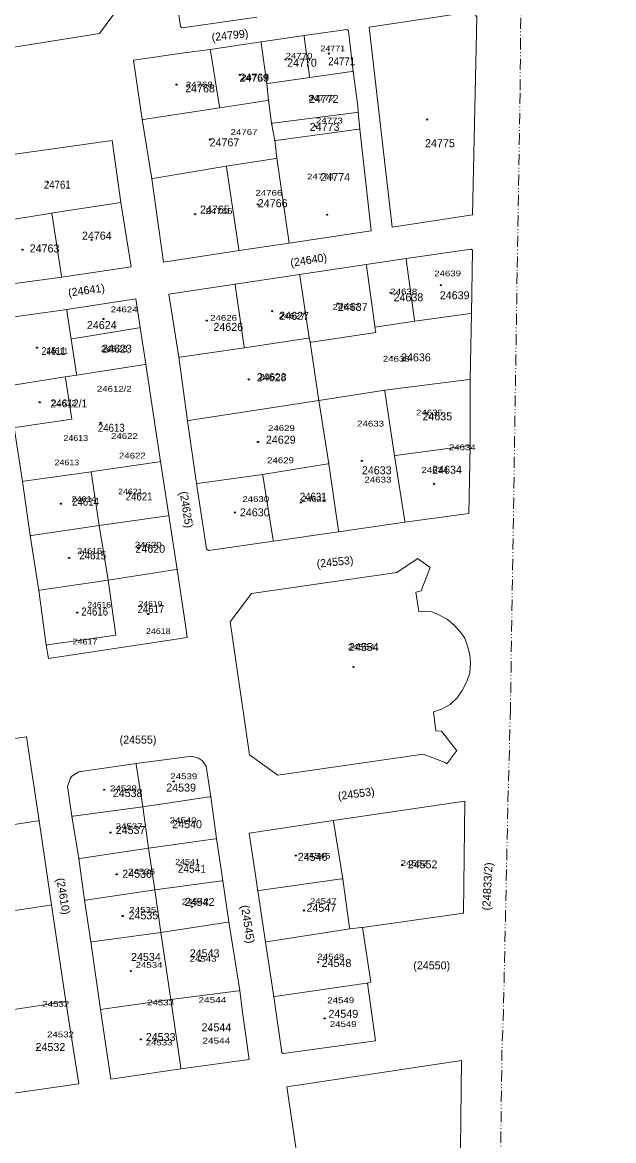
# Model space of a CAD drawing. Extents: x 649608 to 651081, y 237980 to 241202.
# Drawn here: x 650339 to 650605, y 239441 to 239944 of the extents above; entities that cross this region are included whole.
import ezdxf

# ---------------------------------------------------------------- set-up
doc = ezdxf.new("R2010")
doc.units = 0
doc.header["$PDMODE"] = 32
doc.header["$PDSIZE"] = 0.5
doc.linetypes.add('DASH_DOUBLE_DOT', pattern=[9.2, 5, -1.2, 0.3, -1.2, 0.3, -1.2])
for name, color, linetype in [('19', 7, 'Continuous'), ('20', 7, 'Continuous'), ('6', 7, 'Continuous')]:
    doc.layers.add(name, color=color, linetype=linetype)
for name, color, linetype, lineweight in [('3', 7, 'Continuous', 13), ('5', 7, 'Continuous', 13), ('52', 7, 'DASH_DOUBLE_DOT', 13)]:
    doc.layers.add(name, color=color, linetype=linetype, lineweight=lineweight)

msp = doc.modelspace()

# ---------------------------------------------------------------- linework, layer by layer
at = {"layer": '3'}
for p, q in [((650388.272, 239833.948), (650357.01, 239829.262)), ((650498.192, 239485.801), (650494.588, 239511.725))]:
    msp.add_line(p, q, dxfattribs=at)
for points in [[(650379.366, 240006.183), (650386.357, 239955.842), (650374.029, 239938.824), (650309.84, 239928.724), (650300.505, 239993.965)], [(650541.896, 239857.35), (650505.729, 239851.839), (650495.324, 239941.714), (650540.294, 239948.511), (650542.677, 239948.068), (650543.767, 239946.296)], [(650442.311, 239687.015), (650507.764, 239696.364), (650516.54, 239702.276), (650517.154, 239702.698), (650522.83, 239698.633), (650518.685, 239688.139), (650516.424, 239687.616), (650517.648, 239678.967), (650520.433, 239679.099), (650523.564, 239678.716), (650526.782, 239677.466), (650530.542, 239675.342), (650533.559, 239672.695), (650536.443, 239669.593), (650538.447, 239666.861), (650539.773, 239662.869), (650540.677, 239659.443), (650540.997, 239655.798), (650540.595, 239651.375), (650539.316, 239647.477), (650537.275, 239643.361), (650535.02, 239640.115), (650531.858, 239637.088), (650527.953, 239634.989), (650524.265, 239633.829), (650525.363, 239625.233), (650527.891, 239625.14), (650534.407, 239616.759), (650534.882, 239616.42), (650530.279, 239610.413), (650529.63, 239610.933), (650519.725, 239614.737), (650454.269, 239605.236), (650441.468, 239614.46), (650432.74, 239674.295)], [(650458.309, 239465.099), (650536.901, 239476.918), (650535.05, 239318.891), (650481.294, 239310.911)]]:
    msp.add_lwpolyline(points, close=True, dxfattribs=at)
for points in [[(650444.775, 239946.285), (650411.125, 239941.373), (650410.377, 239941.975), (650405.07, 239979.206), (650402.654, 239996.132)], [(650488.095, 239921.796), (650486.117, 239940.058), (650485.368, 239940.661), (650466.029, 239937.979), (650446.664, 239935.198), (650423.852, 239931.653)], [(650423.852, 239931.653), (650412.235, 239930.218), (650389.198, 239926.874), (650393.187, 239900.129), (650397.48, 239873.581)], [(650490.451, 239903.516), (650490.196, 239906.165), (650488.095, 239921.796)], [(650496.295, 239850.186), (650491.187, 239895.879), (650490.451, 239903.516)], [(650321.799, 239853.182), (650317.627, 239882.113), (650379.619, 239890.818), (650383.547, 239862.808), (650388.272, 239833.948)], [(650397.48, 239873.581), (650402.708, 239836.053), (650436.814, 239841.284), (650459.347, 239844.508), (650496.295, 239850.186)], [(650357.01, 239829.262), (650326.82, 239825.19), (650325.994, 239825.713), (650321.799, 239853.182)], [(650511.937, 239837.685), (650541.236, 239841.916), (650541.884, 239841.364), (650541.464, 239812.971)], [(650409.675, 239793.272), (650405.196, 239821.584), (650435.026, 239826.183), (650464.05, 239830.541), (650494.054, 239834.94), (650511.937, 239837.685)], [(650392.332, 239806.607), (650390.258, 239819.533), (650359.246, 239814.696)], [(650359.246, 239814.696), (650327.911, 239810.334), (650332.626, 239780.357), (650335.48, 239761.64), (650339.366, 239737.428), (650342.823, 239713.047), (650346.63, 239688.414), (650350.01, 239663.76), (650350.962, 239657.72), (650413.463, 239667.216)], [(650541.464, 239812.971), (650540.883, 239783.388), (650540.883, 239783.36), (650540.878, 239753.602), (650540.262, 239722.952)], [(650401.384, 239746.357), (650397.603, 239771.089), (650394.853, 239790.078), (650392.332, 239806.607)], [(650452.216, 239710.482), (650423.043, 239706.324), (650422.196, 239707.151), (650417.601, 239736.457), (650413.598, 239764.666), (650409.675, 239793.272)], [(650413.463, 239667.216), (650412.632, 239672.808), (650408.903, 239697.788), (650405.219, 239722.022), (650401.384, 239746.357)], [(650540.262, 239722.952), (650511.468, 239719.039), (650481.616, 239714.738), (650452.216, 239710.482)], [(650284.846, 239575.429), (650278.795, 239613.56), (650341.039, 239622.462), (650346.869, 239584.804), (650352.295, 239546.902), (650358.829, 239503.479)], [(650361.555, 239586.833), (650359.535, 239600.131), (650360.695, 239603.67), (650361.559, 239604.779), (650364.59, 239606.738), (650390.419, 239610.578)], [(650390.419, 239610.578), (650415.491, 239613.879), (650418.522, 239612.934), (650420.295, 239611.727), (650422.032, 239609.303), (650424.049, 239595.534), (650426.7, 239576.72), (650429.501, 239557.755), (650432.255, 239539.238), (650437.089, 239508.366), (650438.17, 239499.693)], [(650537.787, 239543.236), (650538.446, 239593.62), (650479.217, 239584.865)], [(650374.421, 239499.815), (650370.011, 239530.262), (650367.233, 239548.978), (650364.607, 239567.792), (650361.555, 239586.833)], [(650479.217, 239584.865), (650441.39, 239579.121), (650445.262, 239553.321), (650448.655, 239530.156), (650452.412, 239505.573)], [(650494.588, 239511.725), (650496.074, 239512.109), (650492.393, 239536.815), (650537.787, 239543.236)], [(650452.412, 239505.573), (650456.032, 239480.584), (650456.722, 239480.017), (650498.192, 239485.801)], [(650358.829, 239503.479), (650364.595, 239466.403), (650333.35, 239461.895)], [(650410.619, 239473.149), (650379.022, 239468.552), (650374.421, 239499.815)], [(650438.17, 239499.693), (650441.38, 239477.395), (650410.619, 239473.149)]]:
    msp.add_lwpolyline(points, dxfattribs=at)
at = {"layer": '5'}
msp.add_line((650374.421, 239499.815), (650406.058, 239504.324), dxfattribs=at)
for points in [[(650468.63, 239919.116), (650468.561, 239919.616), (650466.098, 239937.479), (650466.029, 239937.979)], [(650446.664, 239935.198), (650446.734, 239934.698), (650449.29, 239916.309), (650450.08, 239908.831), (650451.448, 239898.542), (650452.837, 239890.711), (650453.799, 239882.759), (650459.347, 239844.508)], [(650428.122, 239905.378), (650428.041, 239905.878), (650423.933, 239931.153), (650423.852, 239931.653)], [(650468.63, 239919.116), (650487.595, 239921.727), (650488.095, 239921.796)], [(650449.29, 239916.309), (650449.79, 239916.382), (650468.63, 239919.116)], [(650450.08, 239908.831), (650449.58, 239908.752), (650428.122, 239905.378)], [(650428.122, 239905.378), (650393.687, 239900.204), (650393.187, 239900.129)], [(650490.451, 239903.516), (650489.698, 239903.42), (650451.948, 239898.606), (650451.448, 239898.542)], [(650491.187, 239895.879), (650490.687, 239895.812), (650453.337, 239890.778), (650452.837, 239890.711)], [(650453.799, 239882.759), (650453.299, 239882.681), (650430.986, 239879.215)], [(650430.986, 239879.215), (650397.98, 239873.665), (650397.48, 239873.581)], [(650436.814, 239841.284), (650436.737, 239841.784), (650431.063, 239878.715), (650430.986, 239879.215)], [(650352.561, 239858.096), (650353.061, 239858.172), (650383.547, 239862.808)], [(650352.561, 239858.096), (650322.299, 239853.262), (650321.799, 239853.182)], [(650357.01, 239829.262), (650356.933, 239829.762), (650352.561, 239858.096)], [(650515.863, 239809.476), (650515.793, 239809.976), (650512.007, 239837.185), (650511.937, 239837.685)], [(650497.906, 239806.857), (650497.837, 239807.357), (650494.123, 239834.44), (650494.054, 239834.94)], [(650439.225, 239797.451), (650439.152, 239797.951), (650435.099, 239825.683), (650435.026, 239826.183)], [(650464.05, 239830.541), (650464.125, 239830.041), (650468.35, 239801.932), (650468.836, 239800.042), (650472.705, 239773.795), (650477.182, 239745.333)], [(650359.246, 239814.696), (650359.318, 239814.196), (650361.166, 239801.424)], [(650515.863, 239809.476), (650540.964, 239812.903), (650541.464, 239812.971)], [(650361.166, 239801.424), (650361.666, 239801.507), (650391.832, 239806.524), (650392.332, 239806.607)], [(650468.836, 239800.042), (650469.336, 239800.116), (650498.363, 239804.42), (650497.906, 239806.857), (650515.863, 239809.476)], [(650361.166, 239801.424), (650363.612, 239785.742), (650363.69, 239785.242)], [(650468.35, 239801.932), (650467.85, 239801.855), (650439.225, 239797.451)], [(650439.225, 239797.451), (650410.175, 239793.343), (650409.675, 239793.272)], [(650363.69, 239785.242), (650394.353, 239790), (650394.853, 239790.078)], [(650332.626, 239780.357), (650333.126, 239780.435), (650358.508, 239784.395), (650363.69, 239785.242)], [(650358.508, 239784.395), (650358.588, 239783.895), (650361.534, 239765.379), (650335.98, 239761.712), (650335.48, 239761.64)], [(650502.389, 239778.491), (650502.41, 239778.494), (650540.408, 239783.3), (650540.883, 239783.36)], [(650413.598, 239764.666), (650414.098, 239764.743), (650472.705, 239773.795), (650502.389, 239778.491)], [(650502.389, 239778.491), (650502.459, 239778.019), (650506.752, 239748.942)], [(650506.752, 239748.942), (650507.252, 239749.01), (650540.878, 239753.602)], [(650370.248, 239741.72), (650370.748, 239741.794), (650400.884, 239746.283), (650401.384, 239746.357)], [(650506.752, 239748.942), (650511.389, 239719.539), (650511.468, 239719.039)], [(650370.248, 239741.72), (650339.866, 239737.497), (650339.366, 239737.428)], [(650350.01, 239663.76), (650350.51, 239663.832), (650381.346, 239668.296), (650377.791, 239693.026), (650373.858, 239717.536), (650370.248, 239741.72)], [(650477.182, 239745.333), (650476.682, 239745.252), (650447.401, 239740.511)], [(650477.182, 239745.333), (650481.544, 239715.238), (650481.616, 239714.738)], [(650447.401, 239740.511), (650418.101, 239736.525), (650417.601, 239736.457)], [(650447.401, 239740.511), (650447.481, 239740.011), (650452.136, 239710.982), (650452.216, 239710.482)], [(650373.858, 239717.536), (650404.719, 239721.95), (650405.219, 239722.022)], [(650342.823, 239713.047), (650343.323, 239713.119), (650373.858, 239717.536)], [(650377.791, 239693.026), (650408.403, 239697.711), (650408.903, 239697.788)], [(650346.63, 239688.414), (650347.13, 239688.488), (650377.791, 239693.026)], [(650390.419, 239610.578), (650390.498, 239610.078), (650393.517, 239591.04), (650396.094, 239572.376), (650398.846, 239553.635), (650401.621, 239534.498), (650406.058, 239504.324)], [(650393.517, 239591.04), (650423.549, 239595.46), (650424.049, 239595.534)], [(650361.555, 239586.833), (650362.055, 239586.899), (650393.517, 239591.04)], [(650284.846, 239575.429), (650285.346, 239575.505), (650346.369, 239584.728), (650346.869, 239584.804)], [(650483.438, 239558.689), (650479.298, 239584.365), (650479.217, 239584.865)], [(650396.094, 239572.376), (650426.2, 239576.649), (650426.7, 239576.72)], [(650364.607, 239567.792), (650365.107, 239567.865), (650396.094, 239572.376)], [(650398.846, 239553.635), (650429.001, 239557.688), (650429.501, 239557.755)], [(650445.262, 239553.321), (650445.762, 239553.391), (650482.938, 239558.619), (650483.438, 239558.689)], [(650486.635, 239536.172), (650486.564, 239536.672), (650483.438, 239558.689)], [(650367.233, 239548.978), (650367.733, 239549.052), (650398.846, 239553.635)], [(650290.624, 239537.573), (650291.124, 239537.649), (650351.795, 239546.826), (650352.295, 239546.902)], [(650370.011, 239530.262), (650370.511, 239530.329), (650401.621, 239534.498)], [(650401.621, 239534.498), (650431.755, 239539.161), (650432.255, 239539.238)], [(650486.635, 239536.172), (650449.155, 239530.235), (650448.655, 239530.156)], [(650492.393, 239536.815), (650491.893, 239536.759), (650486.635, 239536.172)], [(650452.412, 239505.573), (650452.912, 239505.646), (650494.088, 239511.652), (650494.588, 239511.725)], [(650406.058, 239504.324), (650436.589, 239508.301), (650437.089, 239508.366)], [(650410.619, 239473.149), (650410.546, 239473.649), (650406.058, 239504.324)], [(650327.946, 239498.688), (650328.446, 239498.766), (650358.829, 239503.479)]]:
    msp.add_lwpolyline(points, dxfattribs=at)
at = {"layer": '52'}
msp.add_lwpolyline([(650605.404, 240765.589), (650575.102, 240622.376), (650564.111, 240019.547), (650563.292, 239912.239), (650561.967, 239831.306), (650558.948, 239635.138), (650557.76, 239590.469), (650555.824, 239499.761), (650555.114, 239481.758), (650553.994, 239393.396), (650554.019, 239393.395), (650553.222, 239318.763), (650553.006, 239301.006), (650586.911, 239277.281)], dxfattribs=at)
at = {"layer": '6'}
for p in [(650457.653, 239927.144), (650477.182, 239929.888), (650437.218, 239920.288), (650408.625, 239915.891), (650469.798, 239910.169), (650471.385, 239897.113), (650521.465, 239900.175), (650423.69, 239891.206), (650350.672, 239872), (650445.217, 239862.021), (650417.002, 239857.634), (650476.489, 239857.35), (650370.358, 239846.035), (650339.33, 239841.643), (650504.937, 239822.271), (650527.629, 239825.696), (650481.229, 239817.491), (650451.672, 239813.996), (650375.783, 239810.478), (650422.251, 239809.727), (650345.85, 239797.526), (650377.993, 239795.924), (650505.448, 239793.383), (650441.173, 239783.299), (650347.032, 239773.017), (650522.546, 239766.151), (650374.464, 239763.753), (650445.297, 239755.126), (650492.05, 239746.614), (650524.637, 239736.32), (650387.681, 239731.946), (650356.589, 239727.383), (650464.565, 239727.907), (650434.894, 239723.417), (650391.444, 239707.524), (650360.287, 239702.975), (650363.949, 239678.393), (650395.94, 239677.754), (650488.268, 239653.967), (650407.37, 239602.459), (650376.027, 239598.705), (650378.933, 239579.416), (650410.088, 239583.955), (650412.778, 239565.177), (650462.328, 239569.093), (650510.254, 239564.896), (650381.706, 239560.677), (650415.583, 239546.126), (650466.015, 239544.422), (650384.409, 239541.948), (650419.24, 239521.781), (650472.373, 239521.194), (650388.04, 239517.156), (650475.305, 239495.871), (650423.75, 239490.757), (650392.532, 239486.438), (650346.179, 239482.687)]:
    msp.add_point(p, dxfattribs=at)

# ---------------------------------------------------------------- texts
at = {"layer": '19'}
for s, rotation, p in [('(24799)', 6.275, (650424.632, 239935.401)), ('24770', 359.954, (650458.402, 239923.927)), ('24769', 359.954, (650436.917, 239917.21)), ('24768', 359.954, (650412.503, 239912.418)), ('24772', 359.954, (650468.173, 239907.667)), ('24773', 359.954, (650468.585, 239895.073)), ('24767', 359.954, (650423.504, 239888.104)), ('24775', 359.954, (650520.513, 239887.748)), ('24774', 359.954, (650473.377, 239872.469)), ('24765', 359.954, (650419.191, 239857.882)), ('24766', 359.954, (650445.218, 239860.743)), ('24764', 359.954, (650366.059, 239846.161)), ('24763', 359.954, (650342.538, 239840.415)), ('(24640)', 8.987, (650460.192, 239833.941)), ('(24641)', 7.873, (650360.105, 239820.512)), ('24638', 359.954, (650506.324, 239818.415)), ('24639', 359.954, (650527.143, 239819.336)), ('24637', 359.954, (650481.284, 239814.108)), ('24627', 359.954, (650454.868, 239810.095)), ('24624', 359.954, (650368.295, 239805.948)), ('24626', 359.954, (650425.241, 239805.134)), ('24623', 359.954, (650375.084, 239795.345)), ('24636', 359.954, (650509.687, 239791.422)), ('24628', 359.954, (650444.791, 239782.486)), ('24635', 359.954, (650519.322, 239764.878)), ('24629', 359.954, (650448.871, 239754.383)), ('24633', 359.954, (650492.074, 239740.627)), ('24634', 359.954, (650523.727, 239740.872)), ('(24625)', 278.957, (650410.049, 239732.635)), ('24630', 359.954, (650437.164, 239721.71)), ('24620', 359.954, (650390.124, 239705.311)), ('(24553)', 6.067, (650471.914, 239698.558)), ('24554', 359.954, (650486.216, 239661.094)), ('24539', 359.954, (650404.012, 239597.906)), ('(24553)', 7.661, (650481.525, 239594.052)), ('24538', 359.954, (650379.949, 239595.44)), ('24540', 359.954, (650406.695, 239581.416)), ('24537', 359.954, (650381.254, 239578.817)), ('24546', 359.954, (650463.193, 239566.745)), ('24552', 359.954, (650512.691, 239563.367)), ('24536', 359.954, (650384.19, 239559.123)), ('(24610)', 279.455, (650354.555, 239558.734)), ('24542', 359.954, (650412.349, 239546.476)), ('24547', 359.954, (650467.122, 239543.825)), ('24535', 359.954, (650387.036, 239540.43)), ('24534', 359.954, (650388.177, 239521.717)), ('24543', 359.954, (650414.589, 239523.363)), ('24548', 359.954, (650473.952, 239519.008)), ('(24550)', 359.954, (650515.211, 239517.933)), ('24549', 359.954, (650477.008, 239496.146)), ('24533', 359.954, (650394.793, 239485.68)), ('24544', 359.954, (650419.905, 239490.061)), ('24532', 359.954, (650345.174, 239481.209))]:
    msp.add_text(s, height=3.6, rotation=rotation, dxfattribs=at).set_placement(p)
for s, rotation, width, p in [('24771', 359.954, 0.9, (650476.943, 239924.572)), ('24761', 359.954, 0.9, (650348.94, 239869.091)), ('24611', 359.954, 0.8, (650347.913, 239794.292)), ('24612/1', 359.954, 0.95, (650351.874, 239770.706)), ('24613', 359.954, 0.9, (650373.236, 239759.746)), ('24621', 359.954, 0.9, (650385.774, 239728.84)), ('24631', 359.954, 0.9, (650464.135, 239728.745)), ('24614', 359.954, 0.9, (650361.644, 239726.497)), ('24615', 359.954, 0.9, (650364.888, 239702.349)), ('24616', 359.954, 0.9, (650365.766, 239677.079)), ('24617', 359.954, 0.9, (650391.079, 239678.204)), ('24541', 359.954, 0.95, (650409.181, 239561.379)), ('(24833/2)', 87.101, 1.05, (650549.808, 239544.348)), ('(24545)', 279.03, 1.05, (650437.574, 239546.578))]:
    msp.add_text(s, height=3.6, rotation=rotation, dxfattribs=dict(at, width=width)).set_placement(p)
msp.add_text('(24555)', height=3.6, dxfattribs=at).set_placement((650383.011, 239619.476))
at = {"layer": '20'}
for s, width, p in [('24771', 1.15, (650473.411, 239930.856)), ('24770', 1.25, (650457.731, 239927.549)), ('24768', 1.25, (650412.844, 239914.61)), ('24769', 1.25, (650437.775, 239917.79)), ('24772', 1.25, (650467.872, 239908.6)), ('24773', 1.25, (650471.417, 239898.426)), ('24767', 1.25, (650432.986, 239893.245)), ('24774', 1.25, (650467.402, 239873.245)), ('24766', 1.25, (650444.163, 239865.902)), ('24765', 1.25, (650421.735, 239857.762)), ('24639', 1.25, (650524.613, 239829.644)), ('24638', 1.25, (650504.897, 239821.505)), ('24624', 1.25, (650379.023, 239813.475)), ('24637', 1.25, (650478.866, 239814.637)), ('24626', 1.25, (650423.765, 239809.674)), ('24627', 1.25, (650454.564, 239810.564)), ('24623', 1.25, (650374.548, 239795.807)), ('24636', 1.25, (650501.49, 239791.237)), ('24628', 1.25, (650445.87, 239783.094)), ('24612/2', 1.25, (650372.772, 239777.756)), ('24612', 1.15, (650352.401, 239771.389)), ('24635', 1.25, (650516.459, 239767.073)), ('24629', 1.25, (650449.813, 239760.075)), ('24633', 1.25, (650489.958, 239762.113)), ('24613', 1.15, (650357.727, 239755.62)), ('24622', 1.25, (650379.145, 239756.51)), ('24634', 1.25, (650531.227, 239751.43)), ('24613', 1.15, (650353.726, 239744.63)), ('24622', 1.25, (650382.717, 239747.716)), ('24629', 1.25, (650449.403, 239745.603)), ('24634', 1.25, (650518.915, 239741.244)), ('24633', 1.25, (650493.236, 239736.916)), ('24614', 1.15, (650361.434, 239728.194)), ('24621', 1.15, (650382.31, 239731.548)), ('24630', 1.25, (650438.256, 239728.171)), ('24631', 1.15, (650465.01, 239728.103)), ('24615', 1.15, (650363.972, 239704.8)), ('24620', 1.25, (650389.833, 239707.627)), ('24616', 1.1, (650368.503, 239680.581)), ('24619', 1.1, (650391.599, 239681.073)), ('24618', 1.15, (650394.853, 239668.767)), ('24617', 1.15, (650361.89, 239664.067)), ('24554', 1.25, (650485.683, 239661.7)), ('24539', 1.25, (650405.871, 239603.479)), ('24538', 1.25, (650378.697, 239598.061)), ('24540', 1.25, (650405.565, 239583.682)), ('24537', 1.25, (650381.244, 239581.043)), ('24546', 1.25, (650465.816, 239567.702)), ('24541', 1.15, (650408.021, 239564.997)), ('24552', 1.25, (650509.501, 239564.372)), ('24536', 1.25, (650386.857, 239560.621)), ('24542', 1.25, (650411.025, 239547.097)), ('24547', 1.25, (650468.681, 239547.304)), ('24535', 1.25, (650387.411, 239543.37)), ('24548', 1.25, (650472.053, 239522.352)), ('24534', 1.25, (650390.221, 239518.641)), ('24543', 1.25, (650414.522, 239521.364)), ('24533', 1.25, (650395.4, 239501.724)), ('24544', 1.3, (650418.522, 239502.871)), ('24549', 1.25, (650476.514, 239502.714)), ('24532', 1.25, (650348.242, 239501.076)), ('24549', 1.25, (650477.614, 239492.021)), ('24532', 1.25, (650350.38, 239487.367)), ('24533', 1.25, (650394.76, 239483.719)), ('24544', 1.3, (650420.274, 239484.55))]:
    msp.add_text(s, height=2.6, dxfattribs=dict(at, width=width)).set_placement(p)
msp.add_text('24611', height=2.6, dxfattribs=at).set_placement((650350.054, 239794.79))

doc.saveas('drawing.dxf')
